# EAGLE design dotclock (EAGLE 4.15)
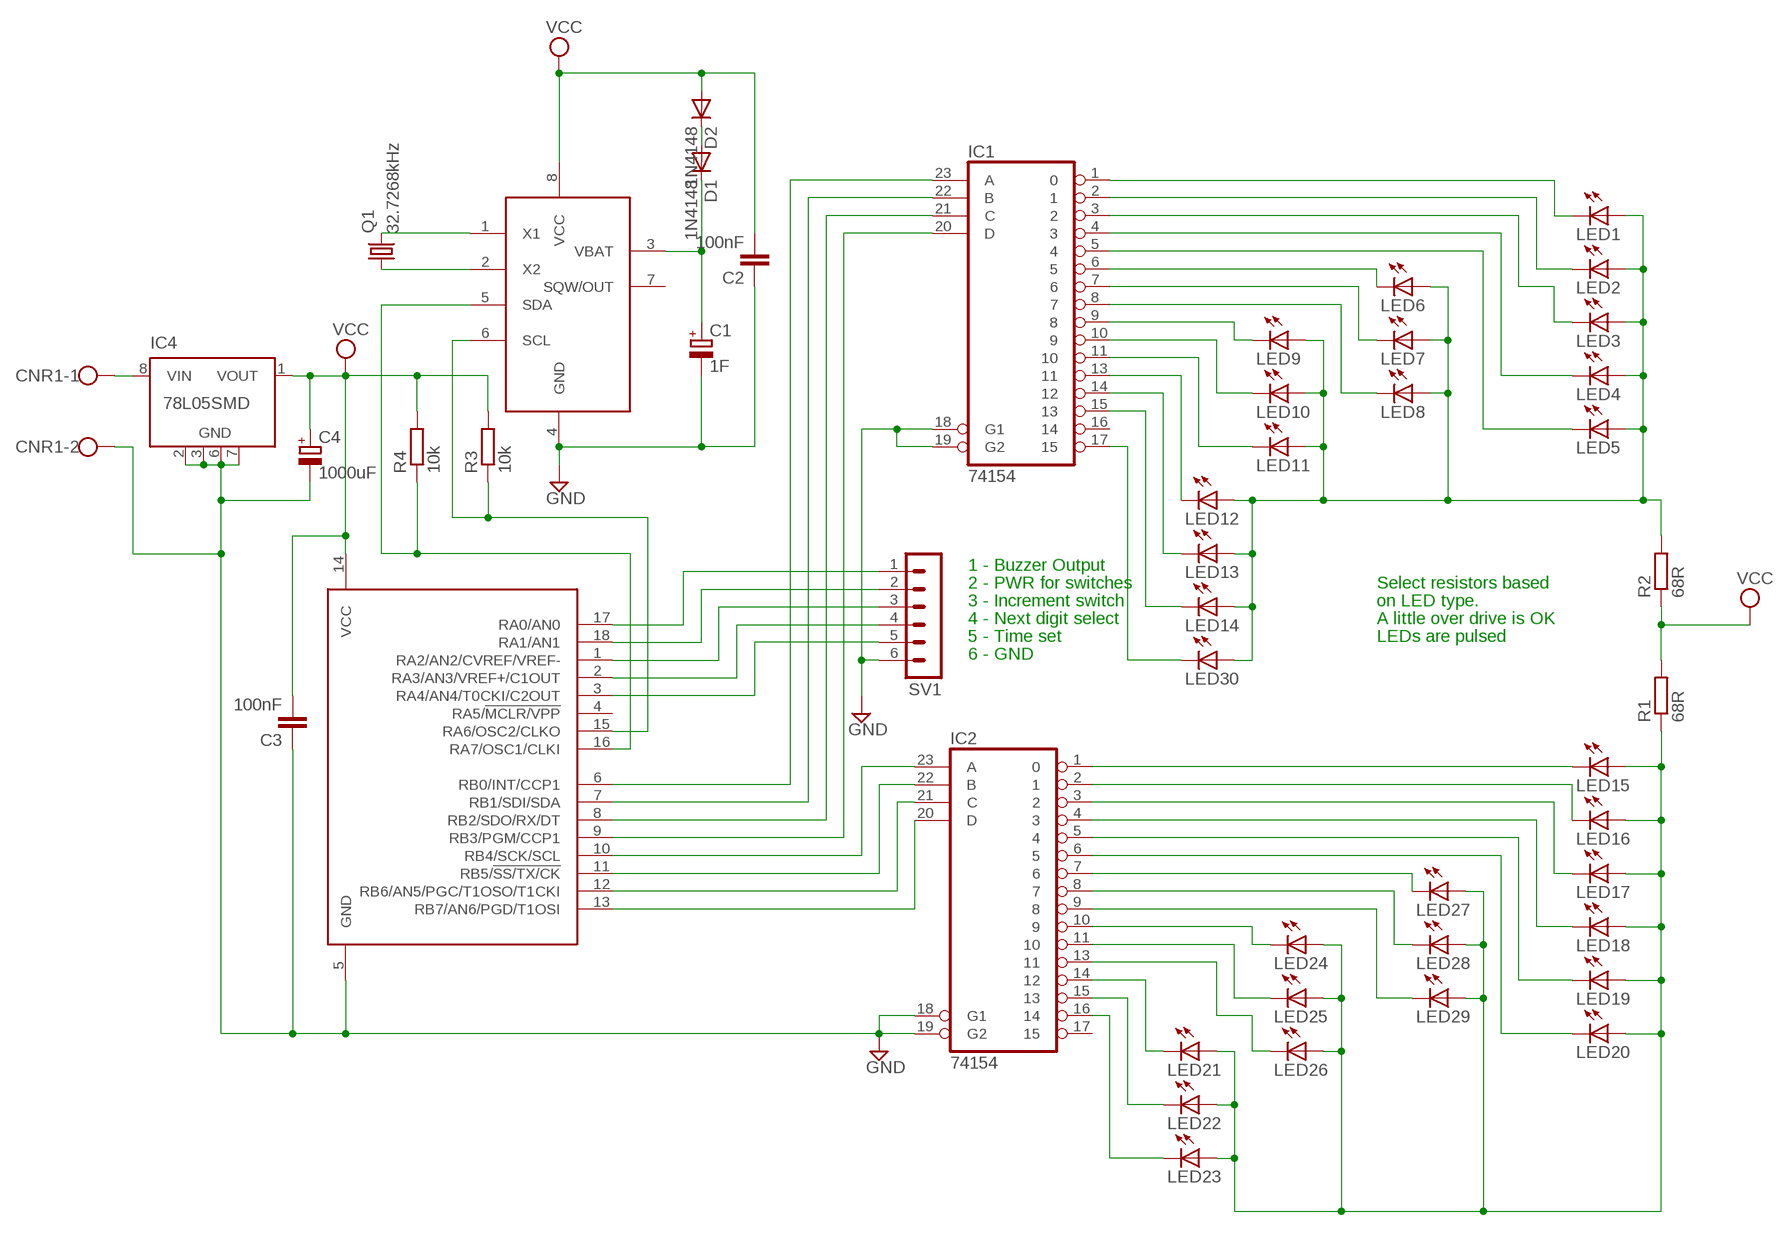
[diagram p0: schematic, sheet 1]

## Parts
C1  1F  CPOL-EUE5-13  [E5-13]
C2  100nF  C2.5/4  [C2.5-4]
C3  100nF  C2.5/4  [C2.5-4]
C4  1000uF  CPOL-EUE5-8.5  [E5-8,5]
CNR1  W237-02P  [W237-132]
D1  1N4148  [DO35-10]
D2  1N4148  [DO35-10]
IC1  74154  [DIL24-3]
IC2  74154  [DIL24-3]
IC4  78L05SMD  [SO08]
LED1  LEDSQR2X5  [LED2X5]
LED2  LEDSQR2X5  [LED2X5]
LED3  LEDSQR2X5  [LED2X5]
LED4  LEDSQR2X5  [LED2X5]
LED5  LEDSQR2X5  [LED2X5]
LED6  LEDSQR2X5  [LED2X5]
LED7  LEDSQR2X5  [LED2X5]
LED8  LEDSQR2X5  [LED2X5]
LED9  LEDSQR2X5  [LED2X5]
LED10  LEDSQR2X5  [LED2X5]
LED11  LEDSQR2X5  [LED2X5]
LED12  LEDSQR2X5  [LED2X5]
LED13  LEDSQR2X5  [LED2X5]
LED14  LEDSQR2X5  [LED2X5]
LED15  LEDSQR2X5  [LED2X5]
LED16  LEDSQR2X5  [LED2X5]
LED17  LEDSQR2X5  [LED2X5]
LED18  LEDSQR2X5  [LED2X5]
LED19  LEDSQR2X5  [LED2X5]
LED20  LEDSQR2X5  [LED2X5]
LED21  LEDSQR2X5  [LED2X5]
LED22  LEDSQR2X5  [LED2X5]
LED23  LEDSQR2X5  [LED2X5]
LED24  LEDSQR2X5  [LED2X5]
LED25  LEDSQR2X5  [LED2X5]
LED26  LEDSQR2X5  [LED2X5]
LED27  LEDSQR2X5  [LED2X5]
LED28  LEDSQR2X5  [LED2X5]
LED29  LEDSQR2X5  [LED2X5]
LED30  LEDSQR2X5  [LED2X5]
Q1  32.7268kHz  CRYTALTC26H  [TC26H]
R1  68R  R-EU_0207/10  [0207/10]
R2  68R  R-EU_0207/10  [0207/10]
R3  10k  R-EU_0207/10  [0207/10]
R4  10k  R-EU_0207/10  [0207/10]
SV1  MA06-1  [MA06-1]
U$1  16F88  [DIL18]
U$2  DS1307  [DIL08]

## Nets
GND: C1.- C2.1 C3.1 C4.- CNR1.2 IC1.18(G1) IC1.19(G2) IC2.18(G1) IC2.19(G2) IC4.2(GND) IC4.3(GND) IC4.6(GND) IC4.7(GND) SV1.6 U$1.5(GND) U$2.4(GND)
N$1: IC1.22(B) U$1.7(RB1/SDI/SDA)
N$2: IC1.23(A) U$1.6(RB0/INT/CCP1)
N$3: Q1.1 U$2.2(X2)
N$4: R3.1 U$1.15(RA6/OSC2/CLKO) U$2.6(SCL)
N$5: IC2.20(D) U$1.13(RB7/AN6/PGD/T1OSI)
N$6: IC2.21(C) U$1.12(RB6/AN5/PGC/T1OSO/T1CKI)
N$7: IC2.22(B) U$1.11(RB5/!SS/TX/CK)
N$8: IC2.23(A) U$1.10(RB4/SCK/SCL)
N$9: IC1.20(D) U$1.9(RB3/PGM/CCP1)
N$10: IC1.21(C) U$1.8(RB2/SDO/RX/DT)
N$11: IC2.1 LED15.K(C)
N$12: IC2.2 LED16.K(C)
N$13: IC2.3 LED17.K(C)
N$14: IC2.4 LED18.K(C)
N$15: IC2.5 LED19.K(C)
N$16: IC2.6 LED20.K(C)
N$17: IC1.1 LED1.K(C)
N$18: IC1.2 LED2.K(C)
N$19: IC1.3 LED3.K(C)
N$20: IC1.4 LED4.K(C)
N$21: IC1.5 LED5.K(C)
N$22: IC1.6 LED6.K(C)
N$23: IC1.7 LED7.K(C)
N$24: IC1.8 LED8.K(C)
N$25: IC1.9 LED9.K(C)
N$26: IC1.10 LED10.K(C)
N$27: IC1.11 LED11.K(C)
N$28: IC1.13 LED12.K(C)
N$29: IC1.14 LED13.K(C)
N$30: IC1.15 LED14.K(C)
N$31: LED1.A LED2.A LED3.A LED4.A LED5.A LED6.A LED7.A LED8.A LED9.A LED10.A LED11.A LED12.A LED13.A LED14.A LED30.A R2.2
N$32: IC2.8 LED28.K(C)
N$33: IC2.9 LED29.K(C)
N$34: IC2.10 LED24.K(C)
N$35: IC2.11 LED25.K(C)
N$36: IC2.13 LED26.K(C)
N$37: IC2.7 LED27.K(C)
N$38: IC2.14 LED21.K(C)
N$39: IC2.15 LED22.K(C)
N$40: IC2.16 LED23.K(C)
N$41: LED15.A LED16.A LED17.A LED18.A LED19.A LED20.A LED21.A LED22.A LED23.A LED24.A LED25.A LED26.A LED27.A LED28.A LED29.A R1.1
N$42: Q1.2 U$2.1(X1)
N$43: IC1.17 LED30.K(C)
N$44: CNR1.1 IC4.8(VIN)
N$45: SV1.3 U$1.1(RA2/AN2/CVREF/VREF-)
N$46: SV1.2 U$1.18(RA1/AN1)
N$47: SV1.1 U$1.17(RA0/AN0)
N$48: SV1.4 U$1.2(RA3/AN3/VREF+/C1OUT)
N$49: SV1.5 U$1.3(RA4/AN4/T0CKI/C2OUT)
N$51: R4.1 U$1.16(RA7/OSC1/CLKI) U$2.5(SDA)
N$53: C1.+ D1.C U$2.3(VBAT)
N$54: D1.A D2.C
VCC: C2.2 C3.2 C4.+ D2.A IC4.1(VOUT) R1.2 R2.1 R3.2 R4.2 U$1.14(VCC) U$2.8(VCC)
Unconnected: IC1.16 IC2.17 IC4.4(NC) IC4.5(NC) U$1.4(RA5/!MCLR/VPP) U$2.7(SQW/OUT)

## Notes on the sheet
- 1 - Buzzer Output
- 2 - PWR for switches | Select resistors based
- 3 - Increment switch | on LED type.
- 4 - Next digit select | A little over drive is OK
- 5 - Time set | LEDs are pulsed
- 6 - GND

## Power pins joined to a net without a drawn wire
GND: IC1.12(GND) IC2.12(GND)
VCC: IC1.24(VCC) IC2.24(VCC)

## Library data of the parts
C1 C4 = rcl:CPOL-EU: POLARIZED CAPACITOR, European symbol
C2 C3 = capacitor-wima:C: CAPACITOR
CNR1 = con-wago-508:W237-02P: WAGO SREW CLAMP
D1 D2 = diode:1N4148: DIODE
IC1 IC2 = 74xx-eu:74*154: 4-line to 16-line data SELECTOR/MULTIPLEXER
IC4 = linear:78L*SMD: Positive VOLTAGE REGULATOR
LED1-LED30 = led:LED: LED
Q1 = crystal:CRYTAL: CRYSTAL
R1-R4 = rcl:R-EU_: RESISTOR, European symbol
SV1 = con-lstb:MA06-1: PIN HEADER
U$1 = microchip:16F88
U$2 = custom:DS1307

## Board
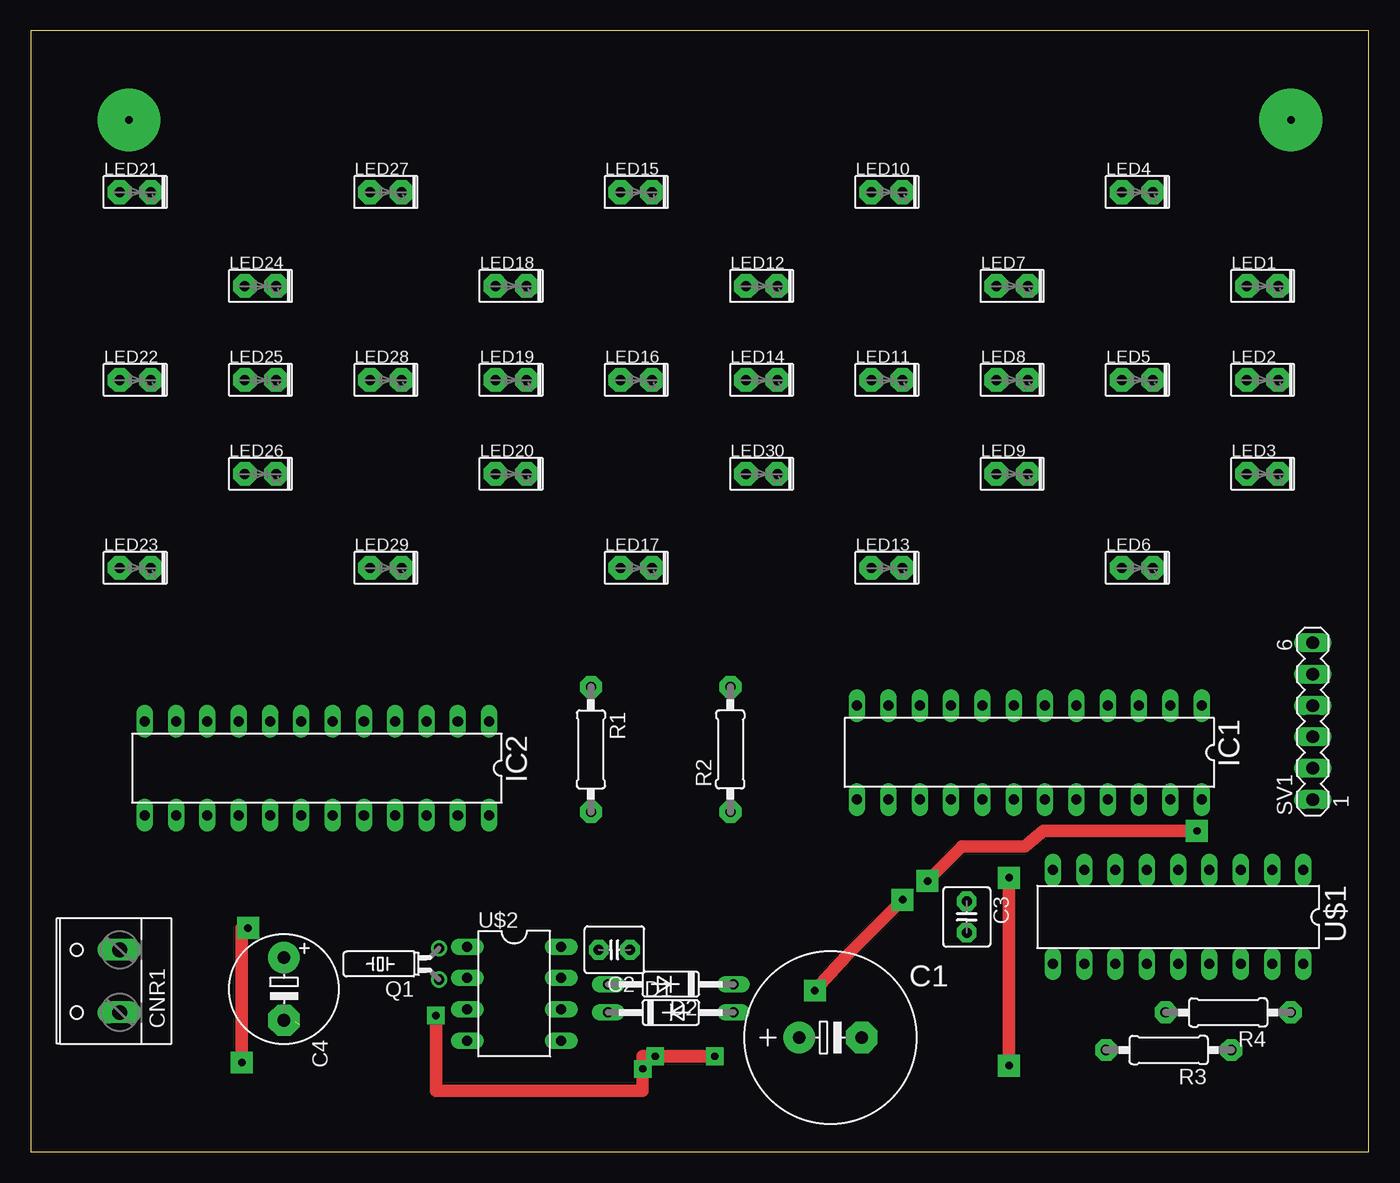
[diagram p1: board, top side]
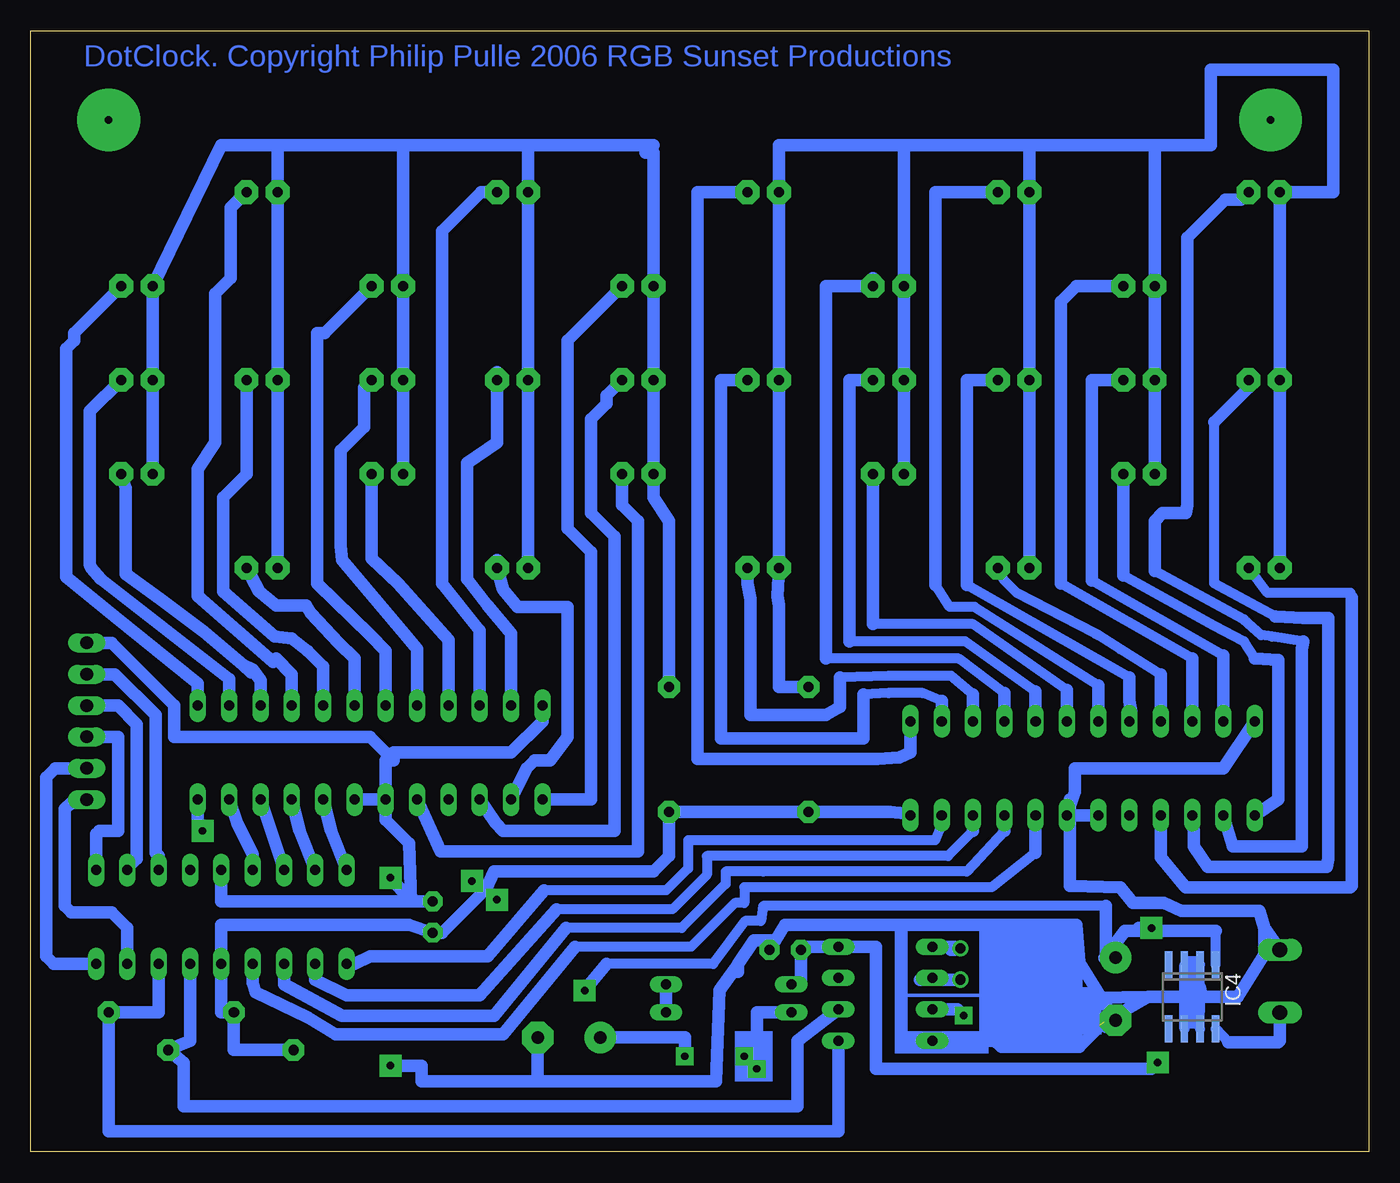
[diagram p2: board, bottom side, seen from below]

Size 108.51 x 90.92 mm. Coordinates in mm from the lower left corner, seen from the top.
Outline: 0,0 108.51,0 108.51,90.92 0,90.92 0,0
Copper layers (1*16): Top 0.035mm / dielectric 1.5mm / Bottom 0.035mm
Design rules "default": minimum track width 10mil, minimum drill 24mil, track to track 8mil, track to pad 8mil, pad to pad 8mil, via to via 8mil, smd to smd 8mil, copper to edge 40mil, drill to drill 8mil, minimum pad ring 10mil, minimum via ring 8mil, stop-mask expansion 4mil, vias tented up to drill 0mil, thermal gap 10mil

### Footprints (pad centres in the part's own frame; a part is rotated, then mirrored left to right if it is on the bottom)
E5-13 = drill 1.016 pad 2.54 round: + -2.54,0 | drill 1.016 pad 2.54 octagon: - 2.54,0
C2.5-4 = drill 0.813 pad 1.6 octagon: 1 -1.27,0; 2 1.27,0
E5-8,5 = drill 1.016 pad 2.54 round: + -2.54,0 | drill 1.016 pad 2.54 octagon: - 2.54,0
W237-132 = drill 1.194 long: 1 -2.54,-0.635; 2 2.54,-0.635
DO35-10 = drill 0.813 long: A 5.08,0; C -5.08,0
DIL24-3 = drill 0.813 long: 1 -13.97,-3.81; 2 -11.43,-3.81; 3 -8.89,-3.81; 4 -6.35,-3.81; 5 -3.81,-3.81; 6 -1.27,-3.81; 7 1.27,-3.81; 8 3.81,-3.81; 9 6.35,-3.81; 10 8.89,-3.81; 11 11.43,-3.81; 12 13.97,-3.81; 13 13.97,3.81; 14 11.43,3.81; 15 8.89,3.81; 16 6.35,3.81; 17 3.81,3.81; 18 1.27,3.81; 19 -1.27,3.81; 20 -3.81,3.81; 21 -6.35,3.81; 22 -8.89,3.81; 23 -11.43,3.81; 24 -13.97,3.81
SO08 = smd 0.6 x 2.2: 1 -1.905,-2.6; 2 -0.635,-2.6; 3 0.635,-2.6; 4 1.905,-2.6; 5 1.905,2.6; 6 0.635,2.6; 7 -0.635,2.6; 8 -1.905,2.6
LED2X5 = drill 0.813 pad 1.93 octagon: A -1.27,0; K 1.27,0
TC26H = drill 0.813 round: 1 -1.27,0; 2 1.27,0
0207/10 = drill 0.813 pad 1.778 octagon: 1 -5.08,0; 2 5.08,0
MA06-1 = drill 1.016 long: 1 -6.35,0; 2 -3.81,0; 3 -1.27,0; 4 1.27,0; 5 3.81,0; 6 6.35,0
DIL18 = drill 0.813 long: 1 -10.16,-3.81; 2 -7.62,-3.81; 3 -5.08,-3.81; 4 -2.54,-3.81; 5 0,-3.81; 6 2.54,-3.81; 7 5.08,-3.81; 8 7.62,-3.81; 9 10.16,-3.81; 10 10.16,3.81; 11 7.62,3.81; 12 5.08,3.81; 13 2.54,3.81; 14 0,3.81; 15 -2.54,3.81; 16 -5.08,3.81; 17 -7.62,3.81; 18 -10.16,3.81
DIL08 = drill 0.813 long: 1 -3.81,-3.81; 2 -1.27,-3.81; 3 1.27,-3.81; 4 3.81,-3.81; 5 3.81,3.81; 6 1.27,3.81; 7 -1.27,3.81; 8 -3.81,3.81

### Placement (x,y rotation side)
C1  64.86,9.27 0 top
C2  47.33,16.38 180 top
C3  75.91,19.05 270 top
C4  20.54,13.2 270 top
CNR1  6.57,13.84 90 top
D1  51.91,11.3 0 top
D2  51.91,13.58 180 top
IC1  80.99,32.38 180 top
IC2  23.2,31.11 180 top
IC4  14.31,12.57 180 bottom
LED1  99.91,70.23 0 top
LED2  99.91,62.61 0 top
LED3  99.91,54.99 0 top
LED4  89.75,77.85 0 top
LED5  89.75,62.61 0 top
LED6  89.75,47.37 0 top
LED7  79.59,70.23 0 top
LED8  79.59,62.61 0 top
LED9  79.59,54.99 0 top
LED10  69.43,77.85 0 top
LED11  69.43,62.61 0 top
LED12  59.27,70.23 0 top
LED13  69.43,47.37 0 top
LED14  59.27,62.61 0 top
LED15  49.11,77.85 0 top
LED16  49.11,62.61 0 top
LED17  49.11,47.37 0 top
LED18  38.95,70.23 0 top
LED19  38.95,62.61 0 top
LED20  38.95,54.99 0 top
LED21  8.47,77.85 0 top
LED22  8.47,62.61 0 top
LED23  8.47,47.37 0 top
LED24  18.63,70.23 0 top
LED25  18.63,62.61 0 top
LED26  18.63,54.99 0 top
LED27  28.79,77.85 0 top
LED28  28.79,62.61 0 top
LED29  28.79,47.37 0 top
LED30  59.27,54.99 0 top
Q1  33.11,15.23 90 top
R1  [0207/10]  45.43,32.63 270 top
R2  [0207/10]  56.73,32.63 90 top
R3  92.29,8.25 180 top
R4  97.12,11.3 180 top
SV1  103.98,34.92 90 top
U$1  93.05,19.05 180 top
U$2  39.2,12.82 270 top

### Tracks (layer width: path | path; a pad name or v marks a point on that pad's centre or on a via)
GND  (via drill 0.6 pad 1.78)  (1 unrouted)
  Top 1.016: v79.34,6.98 v79.34,22.22
  Bottom 0.406: 79.72,28.82 79.59,28.82
  Bottom 0.813: 13.68,12.06 13.68,11.43 | IC4.7 13.68,12.06 | IC4.3 IC4.6 14.95,10.79 13.68,12.06 | 13.68,12.06 13.68,13.33 IC4.2 | 79.59,28.82 79.59,28.57 | IC2.18 21.68,27.3
  Bottom 1.016: IC2.12 11.77,31.11 23.84,31.11 23.84,29.2 IC2.19 | IC1.12 67.02,34.92 69.56,32.38 79.08,32.38 79.72,31.75 | 79.72,31.75 79.72,28.82 IC1.18 79.72,26.92 77.81,25.01 77.69,20.31 | U$1.5 93.05,20.31 77.69,20.31 | 77.69,20.31 C3.1 | 79.72,31.75 79.08,31.75 80.99,33.65 96.86,33.65 96.86,36.19 101.94,41.27 SV1.6 | 77.69,20.31 79.21,22.09 v79.34,22.22 | 8.47,18.16 8.85,19.55 15.2,19.55 16.6,20.19 19.14,20.19 20.15,21.46 24.22,21.59 24.22,28.57 IC2.19 | 8.47,18.16 CNR1.2 | 67.4,5.71 76.8,5.71 76.8,6.98 v79.34,6.98 | 8.47,18.16 8.47,16 10.63,12.57 13.55,12.57 | 13.68,13.33 13.55,12.57 | 17.87,12.57 21.81,10.28 | 17.87,12.57 24.35,12.44 | 13.55,12.57 17.87,12.57 | 20.54,11.17 21.3,10.15 | C4.- 20.54,11.17 | 20.54,11.17 20.15,10.79 | 48.09,17.14 47.33,18.41 23.71,18.41 23.46,15.36 C4.- | 48.09,17.14 49.87,17.14 51.2,15.15 | 51.2,15.15 51.4,14.85 52.67,13.08 52.92,5.71 67.4,5.71 | U$2.4 30.31,9.01 29.81,8.5 23.46,8.5 21.42,10.54 C4.- | 67.4,5.71 C1.- | 79.59,28.57 IC1.19 | IC2.19 IC2.18 | 51.14,14.97 51.14,14.6 | 51.2,15.15 51.14,15.15 51.14,14.97 | 51.14,14.97 51.32,14.97 | 48.09,17.14 48.6,17.14 C2.1
N$1
  Bottom 1.016: U$1.7 IC1.22
N$2
  Bottom 1.016: IC1.23 91.78,26.66 90.51,24.12 U$1.6
N$3
  Bottom 1.016: Q1.1 36.41,13.96 U$2.2
N$4
  Bottom 1.016: U$2.6 46.32,9.01 46.32,3.68 96.1,3.68 96.1,7.23 R3.1 95.59,9.01 U$1.15
N$5
  Bottom 0.813: 64.35,16.63 54.95,16.63 51.4,20.19 50.63,20.19 50.63,21.46 30.57,21.46 27.01,24.25
  Bottom 1.016: U$1.13 90.51,13.71 90.26,12.95 86.07,10.92 83.78,9.52 70.19,9.52 64.35,16.63 | 27.01,24.25 IC2.20
N$6
  Bottom 0.813: 65.11,18.16 55.71,18.16 52.16,21.71 52.16,22.73 49.11,22.73 32.6,22.73 29.55,26.03
  Bottom 1.016: U$1.12 87.97,13.58 83.27,11.04 70.96,11.04 65.11,18.16 | 29.55,26.03 IC2.21
N$7
  Bottom 0.813: 65.88,19.68 56.48,19.68 53.68,22.47 53.68,24 34.12,24 32.09,26.03
  Bottom 1.016: U$1.11 85.43,13.96 82.89,12.7 72.1,12.7 65.88,19.68 | 32.09,26.03 IC2.22
N$8
  Bottom 0.813: 66.89,21.2 56.98,21.2 55.21,22.98 55.21,25.27 51.14,25.27 35.14,25.27 34.63,26.54
  Bottom 1.016: U$1.10 82.26,15.23 80.99,15.87 71.46,15.87 66.89,21.2 | 34.63,26.54 IC2.23
N$9
  Bottom 1.016: IC1.20 84.16,26.03 U$1.9
N$10
  Bottom 1.016: IC1.21 86.7,26.03 U$1.8
N$11
  Bottom 1.016: LED15.K 54.45,77.85 54.45,31.87 39.84,31.87 38.06,32 37.17,32.38 IC2.1
N$12
  Bottom 0.813: 40.98,37.08 38.95,37.21 36.16,37.21 34.63,36.57
  Bottom 1.016: LED16.K 52.54,62.61 52.54,33.52 40.98,33.52 40.98,37.08 | IC2.2 34.63,36.57
N$13
  Bottom 0.813: 42.89,38.48 38.95,38.6 33.87,38.6 32.09,37.08
  Bottom 1.016: LED17.K 50.38,46.1 50.13,44.83 50.13,35.43 44.03,35.43 42.89,36.06 42.89,38.48 | IC2.3 32.09,37.08
N$14
  Bottom 0.813: 29.55,37.21 33.24,40 44.03,40
  Bottom 1.016: IC2.4 29.55,37.21 | 44.03,40 44.03,70.23 40.86,70.23 40.22,70.86 LED18.K
N$15
  Bottom 0.813: 42.13,41.4 32.73,41.4 27.01,37.33
  Bottom 1.016: LED19.K 42.13,62.61 42.13,41.4 | IC2.5 27.01,37.33
N$16
  Bottom 0.813: 24.47,37.46 32.09,42.79 40.22,42.79
  Bottom 1.016: IC2.6 24.47,37.46 | 40.22,42.79 LED20.K
N$17
  Bottom 1.016: IC1.1 94.96,37.97 101.69,43.43 105.63,46.6 105.63,65.15 104.99,65.78 104.99,66.42 LED1.K
N$18
  Bottom 1.016: IC1.2 92.42,38.35 102.83,46.48 103.59,47.37 103.72,47.62 103.72,60.07 LED2.K
N$19
  Bottom 1.016: IC1.3 89.88,38.22 90.51,39.11 91.28,39.49 | 91.28,39.49 90.64,38.86 | 91.28,39.49 94.45,42.16 98.01,44.83 100.8,46.86 100.8,53.84 LED3.K
N$20
  Bottom 1.016: IC1.4 87.34,38.73 88.61,40 88.86,39.75 94.96,45.08 94.96,55.37 93.56,57.53 93.56,69.59 92.29,70.86 92.29,76.58 LED4.K
N$21
  Bottom 1.016: IC1.5 84.8,39.36 86.07,40.63 87.34,41.65 88.73,41.78 92.93,45.46 92.93,53.08 91.02,54.99 LED5.K
N$22
  Bottom 1.016: IC1.6 82.26,40 83.53,41.27 85.81,43.68 86.2,44.32 88.61,44.32 90.01,45.46 LED6.K
N$23
  Bottom 1.016: IC1.7 79.72,40.63 80.99,41.91 85.31,46.1 85.31,66.42 84.67,66.42 LED7.K
N$24
  Bottom 1.016: IC1.8 77.18,40.76 78.45,42.29 83.27,48 83.4,49.14 83.4,56.89 81.5,58.8 81.5,61.97 LED8.K
N$25
  Bottom 1.016: IC1.9 74.64,41.52 78.7,46.1 80.86,48.13 LED9.K
N$26
  Bottom 1.016: IC1.10 72.1,42.29 75.15,46.1 75.15,74.67 71.97,77.85 LED10.K
N$27
  Bottom 1.016: IC1.11 69.56,42.03 71.46,44.32 73.11,46.48 73.11,55.88 70.7,57.53 LED11.K 70.7,63.24
N$28
  Bottom 1.016: IC1.13 63.08,28.57 63.08,48.64 64.99,50.54 64.99,65.78 LED12.K
N$29
  Bottom 1.016: IC1.14 68.29,31.11 67.65,31.75 66.38,31.75 64.99,33.65 64.99,44.19 69.05,44.19 70.19,45.59 LED13.K 70.7,48
N$30
  Bottom 1.016: IC1.15 70.83,26.66 70.19,26.03 61.18,26.03 61.18,49.91 63.08,51.81 63.08,59.43 61.81,60.7 61.81,61.34 LED14.K
N$31
  Bottom 1.016: LED1.A 93.05,81.66 88.48,81.66 | LED1.A LED2.A | LED2.A LED3.A LED2.A | 58.64,81.66 68.16,81.66 | 58.64,81.66 58,81.66 | 68.16,81.66 78.32,81.66 | 78.32,81.66 88.48,81.66 | LED30.A LED14.A | LED30.A LED14.A | LED11.A LED10.A | 68.16,81.66 LED11.A | LED8.A LED9.A | LED8.A LED7.A | 78.32,81.66 LED8.A | LED5.A LED6.A | LED5.A LED4.A | 88.48,81.66 LED5.A | LED1.A LED2.A | R2.2 56.73,51.18 58,53.08 LED30.A | LED11.A LED13.A | LED14.A LED12.A | LED12.A 58,81.02 58.64,81.02 58.64,81.66 | LED14.A LED12.A
N$32
  Bottom 0.813: 19.39,38.48 32.6,45.97
  Bottom 1.016: LED28.K 32.6,62.61 32.6,45.97 | 19.39,38.48 19.39,36.57 19.27,35.68 IC2.8
N$33
  Bottom 0.813: 16.85,38.73 20.15,40.76 21.93,41.91 22.19,42.03 28.54,45.33 29.55,46.35 30.06,47.11 LED29.K
  Bottom 1.016: IC2.9 16.85,38.73
N$34
  Bottom 0.813: 14.31,40 24.98,46.1
  Bottom 1.016: IC2.10 14.31,40 | 24.98,46.1 24.98,68.96 23.71,70.23 LED24.K
N$35
  Bottom 0.813: 11.77,40.25 22.44,46.35
  Bottom 1.016: LED25.K 22.44,62.61 22.44,46.35 | IC2.11 11.77,40.25
N$36
  Bottom 0.813: 9.23,40 10.12,41.4 12.54,42.67 19.9,46.73
  Bottom 1.016: IC2.13 7.33,28.57 7.33,39.87 9.23,40 | 19.9,46.73 LED26.K
N$37
  Bottom 0.813: 35.14,45.97 34,44.19 31.97,44.19 21.93,37.84
  Bottom 1.016: LED27.K 35.14,77.85 35.14,45.97 | IC2.7 21.93,37.84
N$38
  Bottom 0.813: 5.3,41.4 7.84,41.78 8.72,41.91 10.12,43.17 17.36,47.11
  Bottom 1.016: IC2.14 11.01,24.76 5.42,24.76 5.42,40.76 5.3,41.4 | 17.36,47.11 17.36,51.18 16.73,51.81 14.82,51.81 14.69,52.45 14.69,74.16 11.65,77.21 10.38,77.21 LED21.K
N$39
  Bottom 0.813: 12.54,59.18 12.54,46.1 7.58,43.43
  Bottom 1.016: LED22.K 9.74,61.97 12.54,59.18 | 7.58,43.43 5.3,43.3 3.26,43.3 3.26,23.74 3.39,23.11 13.04,23.11 14.19,24.76 14.19,26.03 14.31,26.66 IC2.15
N$40
  Bottom 0.813: 1.36,44.95 1.49,45.33 8.22,45.33 LED23.K
  Bottom 1.016: IC2.16 16.85,23.87 14.95,21.59 14.82,21.46 1.49,21.46 1.36,21.59 1.36,44.95
N$41
  Bottom 1.016: LED23.A LED22.A LED21.A 2.88,77.85 2.88,87.75 12.79,87.75 12.79,81.66 17.36,81.66 | LED25.A LED24.A | LED25.A LED26.A | 17.36,81.66 LED25.A | 17.36,81.66 27.52,81.66 | 27.52,81.66 37.68,81.66 | 37.68,81.66 47.84,81.66 LED15.A LED16.A LED17.A 47.97,45.08 47.84,44.32 47.84,37.71 R1.1 | 37.68,81.66 LED18.A LED19.A LED20.A | 27.52,81.66 LED27.A LED28.A LED29.A
N$42
  Bottom 1.016: U$2.1 33.62,16.63 33.62,16.38 33.87,16.38 Q1.2
N$43
  Bottom 1.016: IC1.17 75.27,24.38 59.27,24.38 59.27,51.18 60.54,52.45 LED30.K
N$44
  Bottom 0.813: 11.39,8.88 IC4.8
  Bottom 1.016: CNR1.1 7.2,9.01 7.33,8.88 11.39,8.88
N$45
  Bottom 1.016: U$1.1 103.21,25.78 102.96,26.03 101.44,26.03 101.44,33.65 SV1.3 102.45,33.65
N$46
  Bottom 1.016: U$1.18 106.64,15.23 107.28,15.87 107.28,30.35 106.52,31.11 SV1.2
N$47
  Bottom 1.016: U$1.17 100.67,18.16 101.94,19.43 105.25,19.43 105.75,19.93 105.75,27.81 105.25,28.32 103.72,28.32 SV1.1
N$48
  Bottom 1.016: SV1.4 101.44,36.19 99.91,34.67 99.91,23.74 100.67,22.98 U$1.2
N$49
  Bottom 1.016: U$1.3 98.13,24 98.39,24.25 98.39,35.43 101.69,38.73 SV1.5 104.23,38.73
N$50  (via drill 0.6 pad 5.08)
  other vias: 7.96,83.69
N$51
  Bottom 1.016: U$2.5 43.02,1.65 102.2,1.65 R4.1 98.13,11.3 U$1.16
N$52  (via drill 0.6 pad 5.08)
  other vias: 102.2,83.69
N$53  (via drill 0.6 pad 1.42)
  Top 1.016: v32.86,11.04 32.86,4.95 49.62,4.95 v49.62,6.73 49.62,7.74 v50.63,7.74 v55.46,7.74
  Bottom 1.016: U$2.3 33.36,11.55 v32.86,11.04 | C1.+ 55.46,9.27 v55.46,7.74 | D1.C 49.62,11.3 49.62,7.74 v50.63,7.74
N$54
  Bottom 1.016: D1.A D2.C
VCC  (via drill 0.6 pad 1.78)
  Top 1.016: v63.59,13.08 66.13,15.87 v70.7,20.44 | v94.58,26.03 82.13,26.03 80.61,24.76 75.53,24.76 v72.73,21.97 | v17.11,7.23 17.11,18.16 v17.61,18.16
  Bottom 0.813: 61.81,15.23 53.17,15.23 50.57,18.73 49.3,18.73 49.11,19.93 21.3,19.93 | IC4.1 12.41,17.9
  Bottom 1.016: IC2.24 37.55,27.43 38.82,27.55 R1.2 R2.1 56.73,24 58,22.73 70.96,22.73 71.59,21.33 | 71.59,21.33 75.15,17.77 C3.2 77.81,18.41 93.05,18.41 U$1.14 93.05,11.3 R4.2 92.04,8.25 R3.2 86.96,8.25 | 61.81,15.23 v63.59,13.08 | v70.7,20.44 71.46,21.2 | 71.46,21.2 71.59,21.33 | IC1.24 94.96,26.92 v94.58,26.03 | v72.73,21.97 72.48,21.97 71.46,21.2 | 12.41,17.9 18.63,17.9 | 18.63,17.9 19.77,17.9 21.3,15.87 | C4.+ 21.42,15.74 21.3,15.87 | 21.3,15.87 21.3,19.93 | v17.11,7.23 17.61,6.73 39.97,6.73 39.97,16.63 U$2.8 46.06,16.63 C2.2 46.06,16.11 | v17.61,18.16 18.63,18.16 18.63,17.9 | 46.06,16.11 46.01,16.11 | 46.06,16.11 46.06,13.58 D2.A
(copper drawn outside any net)
  shapes: Bottom area x8

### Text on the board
Bottom: DotClock. Copyright Philip Pulle 2006 RGB Sunset Productions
